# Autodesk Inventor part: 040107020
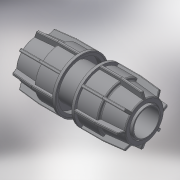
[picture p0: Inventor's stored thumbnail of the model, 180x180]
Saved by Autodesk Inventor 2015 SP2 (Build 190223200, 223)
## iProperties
Created: 2017-08
Part Number: 040107020
Material: Generic
Description: PLASSON IRRIFIT COUPLER 20-20
Document SubType Name: Modeling
Designer: KIM
Density: 1 g/cm^3
Appearance: Default
Author: KIM
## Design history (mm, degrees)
derived "040107.ipt"
feature "Solid1::040107.ipt"
tag "TaggingFeature1"
body "Solid1"
other parameters: "d5" = 30.8, "d6" = 15.84, "d10" = 39, "d22" = 28, "d24" = 1.656, "d25" = 35.1, "d26" = 31.2, "d31" = 0.8, "d49" = 1.95, "d50" = 0, "d58" = 0.4, "d61" = 360 deg, "d78" = 5 deg, "d80" = 22, "d81" = 36, "d82" = 2.16, "d84" = 5 deg, "d85" = 70 deg, "d86" = 37.05, "d87" = 0.36, "d88" = 0, "d89" = 33.15, "d90" = 3.6, "d91" = 0, "d93" = 180 deg, "E_" = 39, "H_" = 72, "l_nut" = 30.8
